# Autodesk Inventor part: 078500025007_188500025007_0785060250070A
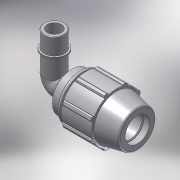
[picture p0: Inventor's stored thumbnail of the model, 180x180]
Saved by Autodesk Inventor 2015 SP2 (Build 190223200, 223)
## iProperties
Created: 2017-02
Part Number: 078500025007_188500025007_0785060250070A
Material: PVC-Piping
Description: PLASSON 90° ELBOW MALE ADAPTOR 25-3/4"
Document SubType Name: Modeling
Designer: KIM
Mass: 92.6774 g
Surface Area: 199.44 cm^2
Volume: 66.1981 cm^3
Density: 1.4 g/cm^3
Appearance: Smooth - White
Author: KIM
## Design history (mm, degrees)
derived "07850.ipt"
feature "Solid1::07850.ipt"
tag "TaggingFeature1"
body "Solid1"
other parameters: "d2" = 25, "d4" = 7.5, "d5" = 22.5, "d7" = 54, "d9" = 12.85714, "d11" = 3, "d13" = 120 deg, "d14" = 37.5, "d15" = 12 deg, "d16" = 46.98, "d18" = 1.25, "d19" = 35 deg, "d20" = 17.5 deg, "d21" = 50.22, "d23" = 0, "d25" = 360 deg, "d27" = 1.08, "d33" = 0.5, "d42" = 33.3, "d43" = 1.62, "d46" = 0.75, "d68" = 3, "d72" = 48, "d73" = 26.441, "d74" = 18, "d75" = 30.40715, "d76" = 18.5087, "d77" = 19.8, "d79" = 10.5764, "d80" = 0.79323, "d83" = 0, "d84" = 0, "d91" = 40.5, "d93" = 58, "d94" = 26.441, "d95" = 18.5087, "d96" = 9, "d97" = 50 deg, "d_" = 25, "E_" = 54, "l_" = 58, "l_2" = 18, "A_1" = 48, "R_" = 26.441
